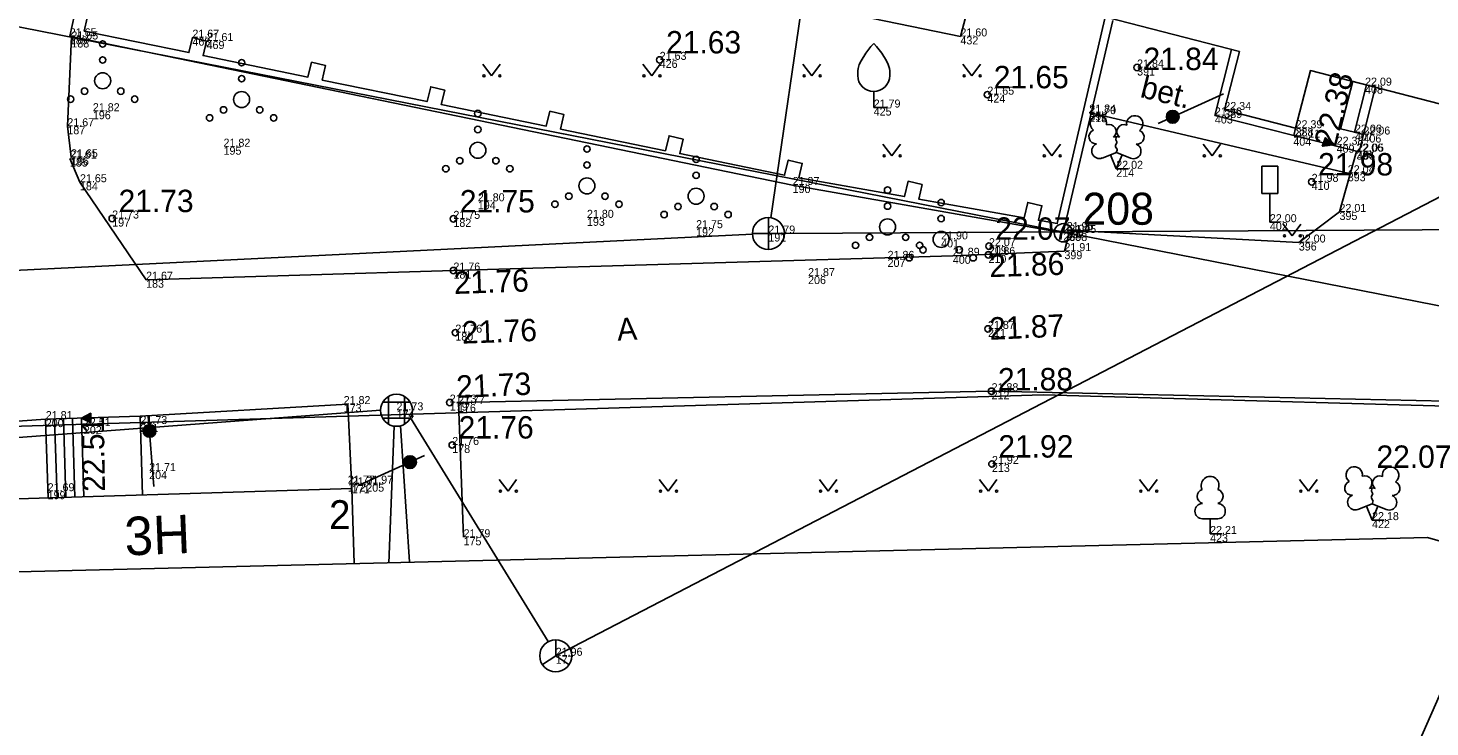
# Model space of a CAD drawing. Extents: x 714279 to 714471, y 6589851 to 6590083.
# Drawn here: x 714329.12 to 714372.9, y 6589960.98 to 6589982.83 of the extents above; entities that cross this region are included whole.
import ezdxf

# ---------------------------------------------------------------- set-up
doc = ezdxf.new("R2010")
doc.units = 0
for name, color, linetype in [('AED', 7, 'Continuous'), ('DKAEV', 7, 'Continuous'), ('DTRASS', 7, 'Continuous'), ('HALJASTUS', 7, 'Continuous'), ('HOONE', 7, 'Continuous'), ('HOONEDET', 7, 'Continuous'), ('KKAEV', 7, 'Continuous'), ('KORGUS', 7, 'Continuous'), ('KTRASS', 7, 'Continuous'), ('LIIKLUS', 7, 'Continuous'), ('MOOTKORG', 7, 'Continuous'), ('MOOTMPUNKT', 7, 'Continuous'), ('MOOTPIIR', 7, 'Continuous'), ('PIIR', 7, 'Continuous'), ('PIIRIMLEITUD', 7, 'Continuous'), ('PUU', 7, 'Continuous'), ('SIKAEV', 7, 'Continuous'), ('SIOHULIIN', 7, 'Continuous'), ('SITRASS', 7, 'Continuous'), ('TEE', 7, 'Continuous')]:
    doc.layers.add(name, color=color, linetype=linetype)

# ---------------------------------------------------------------- blocks, each defined once
blk = doc.blocks.new('SIKAEV')
at = {"layer": 'SIKAEV'}
for p, q in [((0, 1), (0, 0)), ((0, 0), (-0.83, -0.55)), ((0, 0), (0.83, -0.55))]:
    blk.add_line(p, q, dxfattribs=at)
blk.add_circle((0, 0), 1, dxfattribs=at)
blk = doc.blocks.new('RING02')
at = {"layer": 'KORGUS'}
blk.add_circle((0, 0), 0.2, dxfattribs=at)
blk = doc.blocks.new('RING02_2')
at = {"layer": 'KORGUS'}
blk.add_circle((0, 0), 0.2, dxfattribs=at)
blk = doc.blocks.new('RING02_1')
at = {"layer": 'KORGUS'}
blk.add_circle((0, 0), 0.2, dxfattribs=at)
blk = doc.blocks.new('KAKAEV')
at = {"layer": 'KKAEV'}
for p, q in [((0, -1), (0, 1)), ((-1, 0), (1, 0))]:
    blk.add_line(p, q, dxfattribs=at)
blk.add_circle((0, 0), 1, dxfattribs=at)
blk = doc.blocks.new('VQSA')
at = {"layer": 'HALJASTUS'}
for centre, radius in [((0, 2.3), 0.2), ((0, 1.3), 0.2), ((0, 0), 0.5), ((-1.13, -0.65), 0.2), ((1.13, -0.65), 0.2), ((-2, -1.15), 0.2), ((2, -1.15), 0.2)]:
    blk.add_circle(centre, radius, dxfattribs=at)
blk = doc.blocks.new('RTKQRG')
at = {"layer": 'HOONEDET'}
for p, q in [((0, 0), (-0.49, 0.97)), ((0.49, 0.97), (-0.49, 0.97)), ((-0.48, 0.94), (0.21, 0.42)), ((-0.44, 0.97), (0.23, 0.46)), ((-0.42, 0.84), (0.19, 0.37)), ((-0.37, 0.74), (0.17, 0.33)), ((-0.35, 0.97), (0.26, 0.51)), ((-0.32, 0.63), (0.14, 0.28)), ((-0.27, 0.97), (0.28, 0.55)), ((-0.27, 0.53), (0.12, 0.24)), ((-0.22, 0.43), (0.1, 0.19)), ((-0.19, 0.97), (0.3, 0.6)), ((-0.17, 0.33), (0.07, 0.15)), ((-0.11, 0.97), (0.33, 0.64)), ((-0.11, 0.22), (0.05, 0.1)), ((-0.06, 0.12), (0.03, 0.05)), ((-0.02, 0.97), (0.35, 0.69)), ((-0.01, 0.02), (0, 0.01)), ((0, 0), (0.49, 0.97)), ((0.06, 0.97), (0.37, 0.73)), ((0.14, 0.97), (0.39, 0.78)), ((0.22, 0.97), (0.42, 0.83)), ((0.31, 0.97), (0.44, 0.87)), ((0.39, 0.97), (0.46, 0.92)), ((0.47, 0.97), (0.49, 0.96))]:
    blk.add_line(p, q, dxfattribs=at)
blk = doc.blocks.new('PMEHIT_1')
at = {"layer": 'PIIRIMLEITUD'}
blk.add_circle((0, 0), 0.57, dxfattribs=at)
blk = doc.blocks.new('LEHTP2')
at = {"layer": 'PUU'}
for p, q in [((-0.88, 0.67), (0.01, 1.02)), ((0, 0), (-0.35, 0.88)), ((0, 0), (0.36, 0.88)), ((0.01, 1.02), (0.89, 0.66)), ((0.76, 0), (0, 0))]:
    blk.add_line(p, q, dxfattribs=at)
blk.add_lwpolyline([(0.01, 2.01), (-0.03, 1.86), (-0.03, 1.82), (-0.01, 1.76), (0.03, 1.69), (0.04, 1.65), (0.01, 1.58), (-0.04, 1.48), (-0.05, 1.43), (-0.04, 1.4), (-0.02, 1.34), (0.05, 1.22), (0.06, 1.18), (0.05, 1.14), (0.02, 1.07), (0.01, 1.02)], dxfattribs=at)
for centre, radius, start, end in [((-1.114, 2.828), 0.512, 111.50269, 232.51731), ((-1.114, 2.828), 0.512, 350.48556, 111.50017), ((-0.445, 2.327), 0.448, 308.50412, 111.57247), ((0.481, 2.318), 0.45, 67.7016, 230.51262), ((1.158, 2.811), 0.512, 67.6168, 188.63142), ((1.158, 2.811), 0.512, 306.59966, 67.61428), ((-1.262, 2.005), 0.448, 111.43041, 274.49868), ((0.008, 1.535), 0.475, 66.76552, 111.50149), ((1.293, 1.986), 0.448, 264.6183, 67.68657), ((-1.053, 1.117), 0.475, 111.50143, 291.50036), ((1.07, 1.101), 0.475, 247.61661, 67.61554)]:
    blk.add_arc(centre, radius, start, end, dxfattribs=at)
blk = doc.blocks.new('LIIKLM')
at = {"layer": 'LIIKLUS'}
for p, q in [((-0.5, 3.5), (-0.5, 1.8)), ((0.5, 3.5), (-0.5, 3.5)), ((0.5, 3.5), (0.5, 1.8)), ((0.5, 1.8), (-0.5, 1.8)), ((0, 1.8), (0, 0)), ((0.5, 0), (0, 0))]:
    blk.add_line(p, q, dxfattribs=at)
blk = doc.blocks.new('LEHTP1')
at = {"layer": 'PUU'}
for p, q in [((0.48, 0.95), (-0.48, 0.95)), ((0, 0), (0, 0.95)), ((0.76, 0), (0, 0))]:
    blk.add_line(p, q, dxfattribs=at)
for centre, radius, start, end in [((0, 3.04), 0.554, 332.5799, 207.4201), ((-0.34, 2.345), 0.465, 109.02174, 253.14154), ((0.34, 2.345), 0.465, 286.85082, 70.98591), ((-0.475, 1.425), 0.475, 90.0016, 269.3953), ((0.475, 1.425), 0.475, 270.6047, 89.9984)]:
    blk.add_arc(centre, radius, start, end, dxfattribs=at)
blk = doc.blocks.new('VILJA1')
at = {"layer": 'PUU'}
for p, q in [((0, 0), (0, 1)), ((0.8, 0), (0, 0))]:
    blk.add_line(p, q, dxfattribs=at)
for points in [[(-1, 2), (-1, 2.3), (-0.98, 2.43), (-0.91, 2.69), (-0.79, 2.93), (-0.5, 3.4), (-0.18, 3.81), (0, 4)], [(1, 2), (1, 2.3), (0.98, 2.43), (0.91, 2.69), (0.79, 2.93), (0.5, 3.4), (0.18, 3.81), (0, 4)]]:
    blk.add_lwpolyline(points, dxfattribs=at)
blk.add_arc((0, 2), 1, 180, 0, dxfattribs=at)
blk = doc.blocks.new('POINT_DISPLAY')
blk.add_line((0, 0), (0, 0))
blk = doc.blocks.new('SISUUN')
at = {"layer": 'SIOHULIIN'}
blk.add_line((0.5, 0), (4.982, 0), dxfattribs=at)
for radius in [0.399, 0.38, 0.361, 0.342, 0.323, 0.304, 0.285, 0.266, 0.247, 0.228, 0.209, 0.191, 0.172, 0.153, 0.134, 0.115, 0.0959, 0.0769, 0.058, 0.0391, 0.0201, 0.00122]:
    blk.add_circle((3.989, 0), radius, dxfattribs=at)
blk.add_blockref('POINT_DISPLAY', (0, 0), dxfattribs=at)
blk = doc.blocks.new('DRKAEV')
at = {"layer": 'DKAEV'}
for p, q in [((-0.866, 0.5), (0.866, 0.5)), ((-0.5, -0.866), (-0.5, 0.866)), ((0.5, 0.866), (0.5, -0.866)), ((0.866, -0.5), (-0.866, -0.5))]:
    blk.add_line(p, q, dxfattribs=at)
blk.add_circle((0, 0), 1, dxfattribs=at)
blk = doc.blocks.new('MURU_1')
at = {"layer": 'HALJASTUS'}
for p, q in [((-0.93, 1.21), (0, 0)), ((0, 0), (0.89, 1.21))]:
    blk.add_line(p, q, dxfattribs=at)
for centre in [(-0.8, 0), (0.86, 0)]:
    blk.add_circle(centre, 0.11, dxfattribs=at)

msp = doc.modelspace()

# ---------------------------------------------------------------- linework, layer by layer
at = {"layer": 'AED'}
for points in [[(714362.992, 6589983.063), (714361.448, 6589976.429), (714352.996, 6589977.921), (714330.419, 6589982.569), (714330.563, 6589983.236)], [(714330.959, 6589983.144), (714330.874, 6589982.731), (714334.14, 6589982.058), (714334.251, 6589982.526), (714334.692, 6589982.421), (714334.584, 6589981.967), (714337.859, 6589981.293), (714337.97, 6589981.76), (714338.411, 6589981.655), (714338.303, 6589981.201), (714341.58, 6589980.526), (714341.692, 6589980.994), (714342.133, 6589980.889), (714342.024, 6589980.435), (714345.302, 6589979.76), (714345.413, 6589980.228), (714345.854, 6589980.123), (714345.746, 6589979.669), (714349.023, 6589978.994), (714349.135, 6589979.462), (714349.576, 6589979.357), (714349.468, 6589978.903), (714352.745, 6589978.228), (714352.857, 6589978.7), (714353.298, 6589978.595), (714353.19, 6589978.141), (714356.485, 6589977.559), (714356.599, 6589978.039), (714357.04, 6589977.934), (714356.932, 6589977.48), (714360.227, 6589976.898), (714360.341, 6589977.379), (714360.782, 6589977.274), (714360.674, 6589976.819), (714361.258, 6589976.716), (714362.749, 6589983.12)]]:
    msp.add_lwpolyline(points, dxfattribs=at)
at = {"layer": 'DTRASS'}
for points in [[(714340.125, 6589970.88), (714324.95, 6589969.733)], [(714345.36, 6589963.649), (714341.066, 6589970.644)], [(714340.38, 6589966.107), (714340.556, 6589970.384)], [(714341.031, 6589966.142), (714340.746, 6589970.39)]]:
    msp.add_lwpolyline(points, dxfattribs=at)
at = {"layer": 'HOONE'}
for points in [[(714368.084, 6590003.497), (714362.833, 6589983.153), (714366.948, 6589982.091), (714366.479, 6589980.273), (714368.704, 6589979.699), (714369.168, 6589981.497), (714375.054, 6589979.978), (714385.707, 6590021.254), (714379.88, 6590022.758), (714380.346, 6590024.563), (714378.09, 6590025.145), (714377.63, 6590023.366), (714373.521, 6590024.426), (714369.05, 6590007.103), (714363.815, 6590008.455), (714364.534, 6590011.243), (714349.394, 6590015.151), (714346.235, 6590002.913), (714361.396, 6589999), (714362.901, 6590004.835), (714368.084, 6590003.497)], [(714366.702, 6589982.154), (714366.183, 6589980.094), (714368.647, 6589979.473), (714368.704, 6589979.699)], [(714368.647, 6589979.473), (714370.687, 6589978.958), (714370.823, 6589979.498), (714370.546, 6589979.568), (714370.921, 6589981.055)], [(714370.546, 6589979.568), (714370.111, 6589979.677), (714370.486, 6589981.165)], [(714370.823, 6589979.498), (714371.198, 6589980.986)], [(714329.741, 6589968.139), (714329.664, 6589970.604), (714332.618, 6589970.697), (714332.696, 6589968.232)], [(714329.944, 6589970.613), (714330.021, 6589968.148)], [(714330.221, 6589970.621), (714330.298, 6589968.157)], [(714330.501, 6589970.63), (714330.579, 6589968.165)], [(714330.782, 6589970.639), (714330.859, 6589968.174)], [(714326.496, 6589965.774), (714326.425, 6589968.035), (714339.231, 6589968.437), (714339.305, 6589966.095)]]:
    msp.add_lwpolyline(points, dxfattribs=at)
at = {"layer": 'KTRASS'}
for points in [[(714352.31, 6589976.898), (714353.447, 6589984.68)], [(714321.04, 6589974.878), (714351.74, 6589976.38)], [(714352.737, 6589976.407), (714379.9, 6589976.563)]]:
    msp.add_lwpolyline(points, dxfattribs=at)
at = {"layer": 'MOOTPIIR'}
msp.add_lwpolyline([(714325.392, 6590064.148), (714418.405, 6590047.495), (714428.059, 6590039.059), (714392.952, 6589961.13), (714372.822, 6589966.903), (714302.696, 6589965.199), (714319.941, 6590042.637), (714325.392, 6590064.148)], dxfattribs=at)
at = {"layer": 'PIIR'}
for points in [[(714313.433, 6589985.9), (714378.228, 6589973.152), (714405.629, 6590034.791), (714332.408, 6590052.951), (714332.595, 6590052.951)], [(714305.517, 6589967.896), (714327.878, 6589970.35), (714360.817, 6589971.365), (714377.13, 6589970.9), (714368.352, 6589950.974)]]:
    msp.add_lwpolyline(points, dxfattribs=at)
at = {"layer": 'SITRASS'}
msp.add_lwpolyline([(714345.596, 6589963.208), (714378.141, 6589980.11), (714375.32, 6589981.011)], dxfattribs=at)
at = {"layer": 'TEE'}
for points in [[(714336.001, 6589992.726), (714337.015, 6589997.295), (714360.881, 6589992.639), (714358.236, 6589982.565), (714334.814, 6589987.381), (714335.678, 6589991.274)], [(714330.459, 6589978.789), (714330.344, 6589979.758), (714330.474, 6589982.558)], [(714362.259, 6589980.186), (714370.333, 6589978.288)], [(714370.603, 6589978.964), (714370.075, 6589977.079), (714368.804, 6589976.123), (714361.555, 6589976.513)], [(714330.424, 6589978.748), (714330.738, 6589978.008), (714332.804, 6589974.961), (714342.402, 6589975.247), (714357.999, 6589975.709), (714361.484, 6589975.854), (714361.637, 6589976.421)], [(714375.994, 6589970.826), (714374.365, 6589971.147), (714359.209, 6589971.476), (714342.555, 6589971.127)], [(714339.108, 6589971.074), (714332.618, 6589970.697)], [(714339.231, 6589968.437), (714339.108, 6589971.074)], [(714342.718, 6589966.911), (714342.555, 6589971.127)], [(714329.664, 6589970.604), (714308.745, 6589969.083), (714303.506, 6589968.747)]]:
    msp.add_lwpolyline(points, dxfattribs=at)

# ---------------------------------------------------------------- block references
at = {"layer": 'DKAEV', "xscale": 0.5, "yscale": 0.5}
msp.add_blockref('DRKAEV', (714340.625, 6589970.879), dxfattribs=at)
at = {"layer": 'HALJASTUS'}
for name, p, xscale, yscale in [('VQSA', (714331.447, 6589981.179), 0.5, 0.5), ('VQSA', (714335.787, 6589980.593), 0.5, 0.5), ('MURU_1', (714343.595, 6589981.334), 0.3, 0.3), ('MURU_1', (714348.595, 6589981.334), 0.3, 0.3), ('MURU_1', (714353.595, 6589981.334), 0.3, 0.3), ('MURU_1', (714358.595, 6589981.334), 0.3, 0.3), ('VQSA', (714343.164, 6589979.005), 0.5, 0.5), ('VQSA', (714346.572, 6589977.895), 0.5, 0.5), ('VQSA', (714349.981, 6589977.572), 0.5, 0.5), ('MURU_1', (714356.095, 6589978.834), 0.3, 0.3), ('MURU_1', (714361.095, 6589978.834), 0.3, 0.3), ('MURU_1', (714366.095, 6589978.834), 0.3, 0.3), ('VQSA', (714355.961, 6589976.612), 0.5, 0.5), ('VQSA', (714357.633, 6589976.221), 0.5, 0.5), ('MURU_1', (714368.595, 6589976.334), 0.3, 0.3), ('MURU_1', (714344.109, 6589968.354), 0.3, 0.3), ('MURU_1', (714349.109, 6589968.354), 0.3, 0.3), ('MURU_1', (714354.109, 6589968.354), 0.3, 0.3), ('MURU_1', (714359.109, 6589968.354), 0.3, 0.3), ('MURU_1', (714364.109, 6589968.354), 0.3, 0.3), ('MURU_1', (714369.109, 6589968.354), 0.3, 0.3)]:
    msp.add_blockref(name, p, dxfattribs=dict(at, xscale=xscale, yscale=yscale))
at = {"layer": 'HOONEDET', "xscale": 0.3}
for p, yscale, rotation in [((714369.859, 6589979.172), 0.30000000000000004, 70.02406185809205), ((714330.782, 6589970.639), -0.3, 90)]:
    msp.add_blockref('RTKQRG', p, dxfattribs=dict(at, yscale=yscale, rotation=rotation))
at = {"layer": 'KKAEV', "xscale": 0.5, "yscale": 0.5}
msp.add_blockref('KAKAEV', (714352.238, 6589976.404), dxfattribs=at)
at = {"layer": 'KORGUS', "xscale": 0.5, "yscale": 0.5}
for name, p in [('RING02', (714348.844, 6589981.832)), ('RING02', (714363.754, 6589981.593)), ('RING02', (714359.077, 6589980.744)), ('RING02', (714369.206, 6589978.019)), ('RING02', (714331.745, 6589976.873)), ('RING02', (714342.401, 6589976.863)), ('RING02_2', (714359.112, 6589975.737)), ('RING02', (714359.127, 6589976.009)), ('RING02_2', (714342.402, 6589975.247)), ('RING02_1', (714359.097, 6589973.424)), ('RING02_1', (714342.462, 6589973.307)), ('RING02_2', (714359.209, 6589971.476)), ('RING02_2', (714342.288, 6589971.121)), ('RING02', (714342.365, 6589969.797)), ('RING02', (714359.22, 6589969.202))]:
    msp.add_blockref(name, p, dxfattribs=at)
at = {"layer": 'LIIKLUS', "xscale": 0.5, "yscale": 0.5}
msp.add_blockref('LIIKLM', (714367.9, 6589976.758), dxfattribs=at)
at = {"layer": 'PIIRIMLEITUD', "xscale": 0.5, "yscale": 0.5}
msp.add_blockref('PMEHIT_1', (714361.448, 6589976.429), dxfattribs=at)
at = {"layer": 'PUU', "xscale": 0.5, "yscale": 0.5}
for name, p in [('VILJA1', (714355.527, 6589980.342)), ('LEHTP2', (714363.102, 6589978.428)), ('LEHTP2', (714371.091, 6589967.447)), ('LEHTP1', (714366.034, 6589967.014))]:
    msp.add_blockref(name, p, dxfattribs=at)
at = {"layer": 'SIKAEV', "xscale": 0.5, "yscale": 0.5}
msp.add_blockref('SIKAEV', (714345.596, 6589963.208), dxfattribs=at)
at = {"layer": 'SIOHULIIN'}
for p, xscale, yscale, rotation in [((714366.683, 6589980.876), 0.5, 0.5, -155.6237938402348), ((714333.065, 6589968.247), 0.5, 0.5, 94.44810383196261), ((714339.231, 6589968.437), 0.49999999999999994, 0.49999999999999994, 24.3762061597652)]:
    msp.add_blockref('SISUUN', p, dxfattribs=dict(at, xscale=xscale, yscale=yscale, rotation=rotation))

# ---------------------------------------------------------------- texts
at = {"layer": 'HOONE'}
msp.add_text('2', height=0.9, dxfattribs=at).set_placement((714338.517, 6589967.17))
msp.add_text('3H', height=1.2, rotation=2.2992, dxfattribs=at).set_placement((714332.152, 6589966.34))
at = {"layer": 'HOONEDET'}
for s, rotation, p in [('22.38', 76.2336, (714369.953, 6589979.068)), ('22.51', 90.895, (714331.521, 6589968.338))]:
    msp.add_text(s, height=0.7, rotation=rotation, dxfattribs=at).set_placement(p)
at = {"layer": 'KORGUS'}
for s, p in [('21.63', (714349.044, 6589982.032)), ('21.84', (714363.954, 6589981.513)), ('21.65', (714359.277, 6589980.944)), ('21.98', (714369.406, 6589978.219)), ('21.73', (714331.945, 6589977.073)), ('21.75', (714342.601, 6589977.063)), ('22.07', (714359.327, 6589976.209)), ('21.88', (714359.409, 6589971.501)), ('21.76', (714342.565, 6589969.997)), ('21.92', (714359.42, 6589969.402)), ('22.07', (714371.229, 6589969.081))]:
    msp.add_text(s, height=0.7, dxfattribs=at).set_placement(p)
for s, rotation, p in [('21.86', 1.8766, (714359.149, 6589975.04)), ('21.76', 1.9622, (714342.424, 6589974.514)), ('21.76', 2.0771, (714342.68, 6589972.962)), ('21.87', 2.6932, (714359.152, 6589973.08)), ('21.73', 2.5744, (714342.505, 6589971.264))]:
    msp.add_text(s, height=0.7, rotation=rotation, dxfattribs=at).set_placement(p)
at = {"layer": 'MOOTKORG'}
for s, p in [('21.65', (714330.419, 6589982.569)), ('21.65', (714330.47, 6589982.469)), ('21.67', (714334.251, 6589982.526)), ('21.60', (714358.236, 6589982.565)), ('21.61', (714334.692, 6589982.421)), ('21.63', (714348.844, 6589981.832)), ('21.84', (714363.754, 6589981.593)), ('21.65', (714359.077, 6589980.744)), ('22.09', (714370.873, 6589981.026)), ('21.79', (714355.527, 6589980.342)), ('22.34', (714366.477, 6589980.266)), ('21.82', (714331.141, 6589980.227)), ('21.84', (714362.259, 6589980.186)), ('21.70', (714362.259, 6589980.135)), ('21.96', (714366.183, 6589980.094)), ('21.67', (714330.344, 6589979.758)), ('22.11', (714368.633, 6589979.401)), ('22.39', (714368.703, 6589979.695)), ('22.06', (714370.558, 6589979.558)), ('22.06', (714370.823, 6589979.498)), ('21.82', (714335.222, 6589979.118)), ('22.38', (714369.986, 6589979.18)), ('22.06', (714370.603, 6589978.964)), ('22.05', (714370.627, 6589978.965)), ('21.61', (714330.424, 6589978.748)), ('21.65', (714330.459, 6589978.789)), ('22.02', (714363.102, 6589978.428)), ('22.04', (714370.333, 6589978.288)), ('21.65', (714330.738, 6589978.008)), ('21.97', (714352.996, 6589977.921)), ('21.98', (714369.206, 6589978.019)), ('21.80', (714343.164, 6589977.412)), ('21.73', (714331.745, 6589976.873)), ('21.75', (714342.401, 6589976.863)), ('21.80', (714346.572, 6589976.895)), ('22.00', (714367.9, 6589976.758)), ('22.01', (714370.075, 6589977.079)), ('21.75', (714349.981, 6589976.572)), ('21.79', (714352.238, 6589976.404)), ('22.04', (714361.448, 6589976.429)), ('21.95', (714361.555, 6589976.513)), ('21.95', (714361.637, 6589976.421)), ('21.90', (714357.633, 6589976.221)), ('22.07', (714359.127, 6589976.009)), ('22.00', (714368.804, 6589976.123)), ('21.86', (714355.961, 6589975.612)), ('21.89', (714357.999, 6589975.709)), ('21.86', (714359.112, 6589975.737)), ('21.91', (714361.484, 6589975.854)), ('21.76', (714342.402, 6589975.247)), ('21.87', (714353.478, 6589975.075)), ('21.67', (714332.804, 6589974.961)), ('21.76', (714342.462, 6589973.307)), ('21.87', (714359.097, 6589973.424)), ('21.82', (714338.974, 6589971.074)), ('21.73', (714342.288, 6589971.121)), ('21.77', (714342.545, 6589971.079)), ('21.88', (714359.209, 6589971.476)), ('21.73', (714340.625, 6589970.879)), ('21.81', (714329.67, 6589970.604)), ('22.51', (714330.861, 6589970.387)), ('21.73', (714332.626, 6589970.452)), ('21.76', (714342.365, 6589969.797)), ('21.71', (714332.899, 6589968.98)), ('21.92', (714359.22, 6589969.202)), ('21.77', (714339.104, 6589968.591)), ('21.71', (714339.228, 6589968.537)), ('21.97', (714339.68, 6589968.587)), ('21.69', (714329.729, 6589968.351)), ('22.18', (714371.091, 6589967.447)), ('21.79', (714342.718, 6589966.911)), ('22.21', (714366.034, 6589967.014)), ('21.96', (714345.596, 6589963.208))]:
    msp.add_text(s, height=0.25, dxfattribs=at).set_placement(p)
at = {"layer": 'MOOTMPUNKT'}
for s, p in [('189', (714330.419, 6589982.319)), ('188', (714330.47, 6589982.219)), ('468', (714334.251, 6589982.276)), ('469', (714334.692, 6589982.171)), ('432', (714358.236, 6589982.315)), ('426', (714348.844, 6589981.582)), ('391', (714363.754, 6589981.343)), ('408', (714370.873, 6589980.776)), ('424', (714359.077, 6589980.494)), ('196', (714331.141, 6589979.977)), ('425', (714355.527, 6589980.092)), ('392', (714362.259, 6589979.936)), ('215', (714362.259, 6589979.885)), ('403', (714366.183, 6589979.844)), ('389', (714366.477, 6589980.016)), ('187', (714330.344, 6589979.508)), ('388', (714368.703, 6589979.445)), ('404', (714368.633, 6589979.151)), ('407', (714370.558, 6589979.308)), ('406', (714370.823, 6589979.248)), ('186', (714330.459, 6589978.539)), ('195', (714335.222, 6589978.868)), ('409', (714369.986, 6589978.93)), ('394', (714370.603, 6589978.714)), ('405', (714370.627, 6589978.715)), ('185', (714330.424, 6589978.498)), ('214', (714363.102, 6589978.178)), ('184', (714330.738, 6589977.758)), ('190', (714352.996, 6589977.671)), ('410', (714369.206, 6589977.769)), ('393', (714370.333, 6589978.038)), ('194', (714343.164, 6589977.162)), ('395', (714370.075, 6589976.829)), ('197', (714331.745, 6589976.623)), ('182', (714342.401, 6589976.613)), ('193', (714346.572, 6589976.645)), ('192', (714349.981, 6589976.322)), ('402', (714367.9, 6589976.508)), ('191', (714352.238, 6589976.154)), ('401', (714357.633, 6589975.971)), ('208', (714361.448, 6589976.179)), ('397', (714361.555, 6589976.263)), ('398', (714361.637, 6589976.171)), ('400', (714357.999, 6589975.459)), ('210', (714359.112, 6589975.487)), ('209', (714359.127, 6589975.759)), ('399', (714361.484, 6589975.604)), ('396', (714368.804, 6589975.873)), ('207', (714355.961, 6589975.362)), ('183', (714332.804, 6589974.711)), ('181', (714342.402, 6589974.997)), ('206', (714353.478, 6589974.825)), ('180', (714342.462, 6589973.057)), ('211', (714359.097, 6589973.174)), ('212', (714359.209, 6589971.226)), ('173', (714338.974, 6589970.824)), ('179', (714342.288, 6589970.871)), ('176', (714342.545, 6589970.829)), ('200', (714329.67, 6589970.354)), ('201', (714332.626, 6589970.202)), ('174', (714340.625, 6589970.629)), ('202', (714330.861, 6589970.137)), ('178', (714342.365, 6589969.547)), ('213', (714359.22, 6589968.952)), ('204', (714332.899, 6589968.73)), ('199', (714329.729, 6589968.101)), ('172', (714339.104, 6589968.341)), ('171', (714339.228, 6589968.287)), ('205', (714339.68, 6589968.337)), ('422', (714371.091, 6589967.197)), ('423', (714366.034, 6589966.764)), ('175', (714342.718, 6589966.661)), ('177', (714345.596, 6589962.958))]:
    msp.add_text(s, height=0.25, dxfattribs=at).set_placement(p)
at = {"layer": 'PIIRIMLEITUD'}
msp.add_text('208', height=1, dxfattribs=at).set_placement((714362.048, 6589976.679))
at = {"layer": 'TEE'}
for s, rotation, p in [('bet.', 346.1136, (714363.818, 6589980.676)), ('A', 3.5592, (714347.531, 6589973.053))]:
    msp.add_text(s, height=0.7, rotation=rotation, dxfattribs=at).set_placement(p)

doc.saveas('drawing.dxf')
